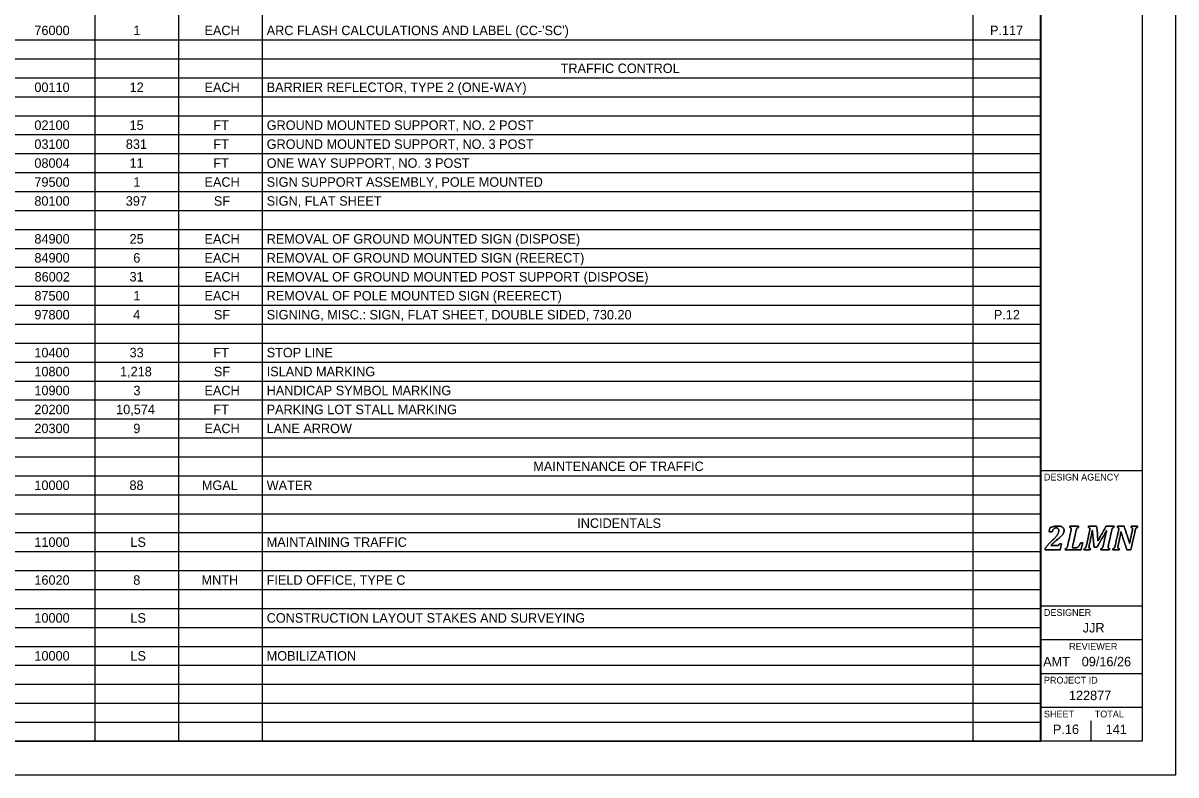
# Model space of a CAD drawing. Extents: x 0 to 34, y 0 to 22.
# Drawn here: x 16.98 to 34, y 0 to 11.11 of the extents above; entities that cross this region are included whole.
import ezdxf

# ---------------------------------------------------------------- set-up
doc = ezdxf.new("R2010")
doc.units = 0
for name, color, linetype in [('SH_Border', 7, 'Continuous'), ('SH_Cut_Line', 7, 'Continuous'), ('SH_Data', 7, 'Continuous'), ('SH_Text', 7, 'Continuous')]:
    doc.layers.add(name, color=color, linetype=linetype)

msp = doc.modelspace()

# ---------------------------------------------------------------- linework, layer by layer
at = {"layer": 'SH_Border'}
for p, q in [((32, 0.5), (32, 21.5)), ((32, 4.5), (33.5, 4.5)), ((32, 2.5), (33.5, 2.5)), ((32, 2), (33.5, 2)), ((32, 1.5), (33.5, 1.5)), ((32, 1), (33.5, 1))]:
    msp.add_line(p, q, dxfattribs=at)
msp.add_lwpolyline([(1.5, 21.5), (33.5, 21.5), (33.5, 0.5), (1.5, 0.5)], close=True, dxfattribs=at)
at = {"layer": 'SH_Cut_Line'}
msp.add_lwpolyline([(0, 0), (34, 0), (34, 22), (0, 22)], close=True, dxfattribs=at)
at = {"layer": 'SH_Data'}
for p, q in [((32.75, 3.5), (32.75, 3.5)), ((32.75, 0.5), (32.75, 0.8)), ((32.375, 0.675), (32.375, 0.675))]:
    msp.add_line(p, q, dxfattribs=at)
for points in [[(32.237, 3.388), (32.246, 3.388), (32.253, 3.389), (32.258, 3.39), (32.263, 3.392), (32.267, 3.394), (32.27, 3.397), (32.273, 3.401), (32.277, 3.408), (32.281, 3.417), (32.281, 3.417), (32.312, 3.417), (32.312, 3.417), (32.312, 3.417), (32.29, 3.326), (32.29, 3.326), (32.29, 3.326), (32.066, 3.326), (32.066, 3.326), (32.066, 3.326), (32.069, 3.343), (32.069, 3.343), (32.078, 3.358), (32.091, 3.375), (32.106, 3.394), (32.122, 3.412), (32.144, 3.435), (32.172, 3.462), (32.197, 3.486), (32.217, 3.506), (32.23, 3.521), (32.243, 3.537), (32.253, 3.551), (32.259, 3.566), (32.266, 3.58), (32.269, 3.595), (32.269, 3.61), (32.269, 3.622), (32.266, 3.632), (32.26, 3.64), (32.253, 3.647), (32.245, 3.65), (32.234, 3.65), (32.22, 3.65), (32.208, 3.646), (32.198, 3.636), (32.188, 3.627), (32.18, 3.613), (32.172, 3.593), (32.172, 3.593), (32.126, 3.593), (32.126, 3.593), (32.126, 3.593), (32.14, 3.654), (32.14, 3.654), (32.166, 3.663), (32.188, 3.669), (32.205, 3.673), (32.223, 3.676), (32.24, 3.678), (32.258, 3.678), (32.278, 3.678), (32.295, 3.675), (32.309, 3.669), (32.322, 3.664), (32.332, 3.656), (32.339, 3.646), (32.345, 3.637), (32.348, 3.626), (32.348, 3.613), (32.348, 3.602), (32.346, 3.591), (32.342, 3.581), (32.339, 3.571), (32.333, 3.56), (32.324, 3.549), (32.315, 3.539), (32.304, 3.526), (32.289, 3.513), (32.275, 3.499), (32.254, 3.482), (32.228, 3.46), (32.216, 3.45), (32.202, 3.438), (32.188, 3.425), (32.174, 3.412), (32.162, 3.4), (32.154, 3.391), (32.154, 3.391), (32.153, 3.388), (32.153, 3.388), (32.153, 3.388), (32.237, 3.388), (32.237, 3.388)], [(32.237, 3.388), (32.237, 3.388), (32.153, 3.388), (32.153, 3.388), (32.153, 3.388), (32.154, 3.391), (32.154, 3.391), (32.162, 3.4), (32.174, 3.412), (32.188, 3.425), (32.202, 3.438), (32.216, 3.45), (32.228, 3.46), (32.254, 3.482), (32.275, 3.499), (32.289, 3.513), (32.304, 3.526), (32.315, 3.539), (32.324, 3.549), (32.333, 3.56), (32.339, 3.571), (32.342, 3.581), (32.346, 3.591), (32.348, 3.602), (32.348, 3.613), (32.348, 3.626), (32.345, 3.637), (32.339, 3.646), (32.332, 3.656), (32.322, 3.664), (32.309, 3.669), (32.295, 3.675), (32.278, 3.678), (32.258, 3.678), (32.24, 3.678), (32.223, 3.676), (32.205, 3.673), (32.188, 3.669), (32.166, 3.663), (32.14, 3.654), (32.14, 3.654), (32.126, 3.593), (32.126, 3.593), (32.126, 3.593), (32.172, 3.593), (32.172, 3.593), (32.18, 3.613), (32.188, 3.627), (32.198, 3.636), (32.208, 3.646), (32.22, 3.65), (32.234, 3.65), (32.245, 3.65), (32.253, 3.647), (32.26, 3.64), (32.266, 3.632), (32.269, 3.622), (32.269, 3.61), (32.269, 3.595), (32.266, 3.58), (32.259, 3.566), (32.253, 3.551), (32.243, 3.537), (32.23, 3.521), (32.217, 3.506), (32.197, 3.486), (32.172, 3.462), (32.144, 3.435), (32.122, 3.412), (32.106, 3.394), (32.091, 3.375), (32.078, 3.358), (32.069, 3.343), (32.069, 3.343), (32.066, 3.326), (32.066, 3.326), (32.066, 3.326), (32.29, 3.326), (32.29, 3.326), (32.29, 3.326), (32.312, 3.417), (32.312, 3.417), (32.312, 3.417), (32.281, 3.417), (32.281, 3.417), (32.277, 3.408), (32.273, 3.401), (32.27, 3.397), (32.267, 3.394), (32.263, 3.392), (32.258, 3.39), (32.253, 3.389), (32.246, 3.388), (32.237, 3.388)], [(32.518, 3.356), (32.527, 3.356), (32.533, 3.357), (32.538, 3.358), (32.542, 3.36), (32.546, 3.362), (32.55, 3.365), (32.554, 3.368), (32.558, 3.372), (32.562, 3.377), (32.567, 3.382), (32.571, 3.388), (32.576, 3.397), (32.58, 3.405), (32.585, 3.415), (32.589, 3.427), (32.589, 3.427), (32.624, 3.427), (32.624, 3.427), (32.624, 3.427), (32.598, 3.326), (32.598, 3.326), (32.598, 3.326), (32.365, 3.326), (32.365, 3.326), (32.365, 3.326), (32.369, 3.343), (32.369, 3.343), (32.376, 3.345), (32.381, 3.348), (32.385, 3.351), (32.389, 3.355), (32.392, 3.36), (32.395, 3.366), (32.398, 3.373), (32.4, 3.382), (32.403, 3.395), (32.403, 3.395), (32.449, 3.605), (32.449, 3.605), (32.452, 3.615), (32.453, 3.625), (32.453, 3.635), (32.453, 3.642), (32.451, 3.647), (32.448, 3.651), (32.444, 3.654), (32.439, 3.656), (32.432, 3.657), (32.432, 3.657), (32.435, 3.674), (32.435, 3.674), (32.435, 3.674), (32.563, 3.674), (32.563, 3.674), (32.563, 3.674), (32.559, 3.657), (32.559, 3.657), (32.552, 3.655), (32.547, 3.652), (32.543, 3.649), (32.539, 3.645), (32.536, 3.64), (32.533, 3.634), (32.531, 3.627), (32.528, 3.618), (32.525, 3.605), (32.525, 3.605), (32.47, 3.356), (32.47, 3.356), (32.47, 3.356), (32.518, 3.356), (32.518, 3.356)], [(32.518, 3.356), (32.518, 3.356), (32.47, 3.356), (32.47, 3.356), (32.47, 3.356), (32.525, 3.605), (32.525, 3.605), (32.528, 3.618), (32.531, 3.627), (32.533, 3.634), (32.536, 3.64), (32.539, 3.645), (32.543, 3.649), (32.547, 3.652), (32.552, 3.655), (32.559, 3.657), (32.559, 3.657), (32.563, 3.674), (32.563, 3.674), (32.563, 3.674), (32.435, 3.674), (32.435, 3.674), (32.435, 3.674), (32.432, 3.657), (32.432, 3.657), (32.439, 3.656), (32.444, 3.654), (32.448, 3.651), (32.451, 3.647), (32.453, 3.642), (32.453, 3.635), (32.453, 3.625), (32.452, 3.615), (32.449, 3.605), (32.449, 3.605), (32.403, 3.395), (32.403, 3.395), (32.4, 3.382), (32.398, 3.373), (32.395, 3.366), (32.392, 3.36), (32.389, 3.355), (32.385, 3.351), (32.381, 3.348), (32.376, 3.345), (32.369, 3.343), (32.369, 3.343), (32.365, 3.326), (32.365, 3.326), (32.365, 3.326), (32.598, 3.326), (32.598, 3.326), (32.598, 3.326), (32.624, 3.427), (32.624, 3.427), (32.624, 3.427), (32.589, 3.427), (32.589, 3.427), (32.585, 3.415), (32.58, 3.405), (32.576, 3.397), (32.571, 3.388), (32.567, 3.382), (32.562, 3.377), (32.558, 3.372), (32.554, 3.368), (32.55, 3.365), (32.546, 3.362), (32.542, 3.36), (32.538, 3.358), (32.533, 3.357), (32.527, 3.356), (32.518, 3.356)], [(32.829, 3.674), (32.829, 3.674), (32.849, 3.461), (32.849, 3.461), (32.849, 3.461), (32.969, 3.674), (32.969, 3.674), (32.969, 3.674), (33.087, 3.674), (33.087, 3.674), (33.087, 3.674), (33.084, 3.657), (33.084, 3.657), (33.077, 3.655), (33.071, 3.652), (33.067, 3.649), (33.064, 3.645), (33.06, 3.64), (33.058, 3.634), (33.055, 3.627), (33.052, 3.618), (33.05, 3.605), (33.05, 3.605), (33.003, 3.395), (33.003, 3.395), (33.002, 3.39), (33.002, 3.387), (33.001, 3.384), (33.001, 3.382), (33.001, 3.379), (33, 3.376), (33, 3.373), (33, 3.369), (33, 3.365), (33, 3.358), (33.002, 3.353), (33.005, 3.349), (33.008, 3.346), (33.014, 3.344), (33.021, 3.343), (33.021, 3.343), (33.018, 3.326), (33.018, 3.326), (33.018, 3.326), (32.89, 3.326), (32.89, 3.326), (32.89, 3.326), (32.893, 3.343), (32.893, 3.343), (32.9, 3.345), (32.906, 3.348), (32.91, 3.351), (32.914, 3.355), (32.917, 3.36), (32.919, 3.366), (32.922, 3.373), (32.925, 3.382), (32.928, 3.395), (32.928, 3.395), (32.951, 3.502), (32.951, 3.502), (32.954, 3.513), (32.957, 3.529), (32.962, 3.548), (32.967, 3.568), (32.972, 3.588), (32.978, 3.609), (32.978, 3.609), (32.973, 3.609), (32.973, 3.609), (32.965, 3.594), (32.957, 3.579), (32.948, 3.563), (32.948, 3.563), (32.833, 3.364), (32.833, 3.364), (32.833, 3.364), (32.792, 3.364), (32.792, 3.364), (32.792, 3.364), (32.775, 3.518), (32.775, 3.518), (32.773, 3.537), (32.772, 3.554), (32.77, 3.569), (32.769, 3.583), (32.768, 3.597), (32.768, 3.611), (32.768, 3.611), (32.764, 3.611), (32.764, 3.611), (32.761, 3.596), (32.758, 3.578), (32.755, 3.558), (32.751, 3.538), (32.747, 3.521), (32.744, 3.507), (32.744, 3.507), (32.72, 3.395), (32.72, 3.395), (32.719, 3.39), (32.718, 3.387), (32.718, 3.384), (32.717, 3.382), (32.717, 3.379), (32.717, 3.376), (32.717, 3.373), (32.716, 3.369), (32.716, 3.365), (32.716, 3.358), (32.718, 3.353), (32.721, 3.349), (32.725, 3.346), (32.73, 3.344), (32.738, 3.343), (32.738, 3.343), (32.734, 3.326), (32.734, 3.326), (32.734, 3.326), (32.641, 3.326), (32.641, 3.326), (32.641, 3.326), (32.644, 3.343), (32.644, 3.343), (32.651, 3.345), (32.657, 3.348), (32.661, 3.351), (32.665, 3.355), (32.668, 3.36), (32.67, 3.366), (32.673, 3.373), (32.676, 3.382), (32.679, 3.395), (32.679, 3.395), (32.725, 3.605), (32.725, 3.605), (32.727, 3.615), (32.728, 3.625), (32.728, 3.635), (32.728, 3.642), (32.727, 3.647), (32.723, 3.651), (32.72, 3.654), (32.715, 3.656), (32.707, 3.657), (32.707, 3.657), (32.711, 3.674), (32.711, 3.674), (32.711, 3.674), (32.829, 3.674), (32.829, 3.674)], [(32.829, 3.674), (32.829, 3.674), (32.711, 3.674), (32.711, 3.674), (32.711, 3.674), (32.707, 3.657), (32.707, 3.657), (32.715, 3.656), (32.72, 3.654), (32.723, 3.651), (32.727, 3.647), (32.728, 3.642), (32.728, 3.635), (32.728, 3.625), (32.727, 3.615), (32.725, 3.605), (32.725, 3.605), (32.679, 3.395), (32.679, 3.395), (32.676, 3.382), (32.673, 3.373), (32.67, 3.366), (32.668, 3.36), (32.665, 3.355), (32.661, 3.351), (32.657, 3.348), (32.651, 3.345), (32.644, 3.343), (32.644, 3.343), (32.641, 3.326), (32.641, 3.326), (32.641, 3.326), (32.734, 3.326), (32.734, 3.326), (32.734, 3.326), (32.738, 3.343), (32.738, 3.343), (32.73, 3.344), (32.725, 3.346), (32.721, 3.349), (32.718, 3.353), (32.716, 3.358), (32.716, 3.365), (32.716, 3.369), (32.717, 3.373), (32.717, 3.376), (32.717, 3.379), (32.717, 3.382), (32.718, 3.384), (32.718, 3.387), (32.719, 3.39), (32.72, 3.395), (32.72, 3.395), (32.744, 3.507), (32.744, 3.507), (32.747, 3.521), (32.751, 3.538), (32.755, 3.558), (32.758, 3.578), (32.761, 3.596), (32.764, 3.611), (32.764, 3.611), (32.768, 3.611), (32.768, 3.611), (32.768, 3.597), (32.769, 3.583), (32.77, 3.569), (32.772, 3.554), (32.773, 3.537), (32.775, 3.518), (32.775, 3.518), (32.792, 3.364), (32.792, 3.364), (32.792, 3.364), (32.833, 3.364), (32.833, 3.364), (32.833, 3.364), (32.948, 3.563), (32.948, 3.563), (32.957, 3.579), (32.965, 3.594), (32.973, 3.609), (32.973, 3.609), (32.978, 3.609), (32.978, 3.609), (32.972, 3.588), (32.967, 3.568), (32.962, 3.548), (32.957, 3.529), (32.954, 3.513), (32.951, 3.502), (32.951, 3.502), (32.928, 3.395), (32.928, 3.395), (32.925, 3.382), (32.922, 3.373), (32.919, 3.366), (32.917, 3.36), (32.914, 3.355), (32.91, 3.351), (32.906, 3.348), (32.9, 3.345), (32.893, 3.343), (32.893, 3.343), (32.89, 3.326), (32.89, 3.326), (32.89, 3.326), (33.018, 3.326), (33.018, 3.326), (33.018, 3.326), (33.021, 3.343), (33.021, 3.343), (33.014, 3.344), (33.008, 3.346), (33.005, 3.349), (33.002, 3.353), (33, 3.358), (33, 3.365), (33, 3.369), (33, 3.373), (33, 3.376), (33.001, 3.379), (33.001, 3.382), (33.001, 3.384), (33.002, 3.387), (33.002, 3.39), (33.003, 3.395), (33.003, 3.395), (33.05, 3.605), (33.05, 3.605), (33.052, 3.618), (33.055, 3.627), (33.058, 3.634), (33.06, 3.64), (33.064, 3.645), (33.067, 3.649), (33.071, 3.652), (33.077, 3.655), (33.084, 3.657), (33.084, 3.657), (33.087, 3.674), (33.087, 3.674), (33.087, 3.674), (32.969, 3.674), (32.969, 3.674), (32.969, 3.674), (32.849, 3.461), (32.849, 3.461), (32.849, 3.461), (32.829, 3.674), (32.829, 3.674)], [(33.137, 3.674), (33.137, 3.674), (33.234, 3.674), (33.234, 3.674), (33.234, 3.674), (33.283, 3.53), (33.283, 3.53), (33.296, 3.49), (33.307, 3.456), (33.315, 3.426), (33.315, 3.426), (33.318, 3.426), (33.318, 3.426), (33.323, 3.455), (33.329, 3.488), (33.337, 3.523), (33.337, 3.523), (33.355, 3.605), (33.355, 3.605), (33.357, 3.615), (33.358, 3.625), (33.358, 3.635), (33.358, 3.642), (33.357, 3.647), (33.353, 3.651), (33.35, 3.654), (33.345, 3.656), (33.337, 3.657), (33.337, 3.657), (33.341, 3.674), (33.341, 3.674), (33.341, 3.674), (33.434, 3.674), (33.434, 3.674), (33.434, 3.674), (33.431, 3.657), (33.431, 3.657), (33.424, 3.655), (33.418, 3.652), (33.414, 3.649), (33.41, 3.645), (33.407, 3.64), (33.405, 3.634), (33.402, 3.627), (33.399, 3.618), (33.396, 3.605), (33.396, 3.605), (33.335, 3.326), (33.335, 3.326), (33.335, 3.326), (33.277, 3.326), (33.277, 3.326), (33.277, 3.326), (33.216, 3.504), (33.216, 3.504), (33.211, 3.518), (33.207, 3.531), (33.204, 3.543), (33.2, 3.556), (33.195, 3.571), (33.19, 3.59), (33.19, 3.59), (33.186, 3.59), (33.186, 3.59), (33.185, 3.579), (33.182, 3.563), (33.179, 3.543), (33.175, 3.523), (33.17, 3.501), (33.165, 3.478), (33.165, 3.478), (33.147, 3.395), (33.147, 3.395), (33.146, 3.39), (33.145, 3.387), (33.145, 3.384), (33.144, 3.382), (33.144, 3.379), (33.144, 3.376), (33.143, 3.373), (33.143, 3.369), (33.143, 3.365), (33.143, 3.358), (33.145, 3.353), (33.148, 3.349), (33.152, 3.346), (33.157, 3.344), (33.164, 3.343), (33.164, 3.343), (33.161, 3.326), (33.161, 3.326), (33.161, 3.326), (33.067, 3.326), (33.067, 3.326), (33.067, 3.326), (33.071, 3.343), (33.071, 3.343), (33.078, 3.345), (33.083, 3.348), (33.087, 3.351), (33.091, 3.355), (33.094, 3.36), (33.097, 3.366), (33.1, 3.373), (33.102, 3.382), (33.105, 3.395), (33.105, 3.395), (33.151, 3.605), (33.151, 3.605), (33.154, 3.615), (33.155, 3.625), (33.155, 3.635), (33.155, 3.642), (33.153, 3.647), (33.15, 3.651), (33.146, 3.654), (33.141, 3.656), (33.134, 3.657), (33.134, 3.657), (33.137, 3.674), (33.137, 3.674)], [(33.137, 3.674), (33.137, 3.674), (33.134, 3.657), (33.134, 3.657), (33.141, 3.656), (33.146, 3.654), (33.15, 3.651), (33.153, 3.647), (33.155, 3.642), (33.155, 3.635), (33.155, 3.625), (33.154, 3.615), (33.151, 3.605), (33.151, 3.605), (33.105, 3.395), (33.105, 3.395), (33.102, 3.382), (33.1, 3.373), (33.097, 3.366), (33.094, 3.36), (33.091, 3.355), (33.087, 3.351), (33.083, 3.348), (33.078, 3.345), (33.071, 3.343), (33.071, 3.343), (33.067, 3.326), (33.067, 3.326), (33.067, 3.326), (33.161, 3.326), (33.161, 3.326), (33.161, 3.326), (33.164, 3.343), (33.164, 3.343), (33.157, 3.344), (33.152, 3.346), (33.148, 3.349), (33.145, 3.353), (33.143, 3.358), (33.143, 3.365), (33.143, 3.369), (33.143, 3.373), (33.144, 3.376), (33.144, 3.379), (33.144, 3.382), (33.145, 3.384), (33.145, 3.387), (33.146, 3.39), (33.147, 3.395), (33.147, 3.395), (33.165, 3.478), (33.165, 3.478), (33.17, 3.501), (33.175, 3.523), (33.179, 3.543), (33.182, 3.563), (33.185, 3.579), (33.186, 3.59), (33.186, 3.59), (33.19, 3.59), (33.19, 3.59), (33.195, 3.571), (33.2, 3.556), (33.204, 3.543), (33.207, 3.531), (33.211, 3.518), (33.216, 3.504), (33.216, 3.504), (33.277, 3.326), (33.277, 3.326), (33.277, 3.326), (33.335, 3.326), (33.335, 3.326), (33.335, 3.326), (33.396, 3.605), (33.396, 3.605), (33.399, 3.618), (33.402, 3.627), (33.405, 3.634), (33.407, 3.64), (33.41, 3.645), (33.414, 3.649), (33.418, 3.652), (33.424, 3.655), (33.431, 3.657), (33.431, 3.657), (33.434, 3.674), (33.434, 3.674), (33.434, 3.674), (33.341, 3.674), (33.341, 3.674), (33.341, 3.674), (33.337, 3.657), (33.337, 3.657), (33.345, 3.656), (33.35, 3.654), (33.353, 3.651), (33.357, 3.647), (33.358, 3.642), (33.358, 3.635), (33.358, 3.625), (33.357, 3.615), (33.355, 3.605), (33.355, 3.605), (33.337, 3.523), (33.337, 3.523), (33.329, 3.488), (33.323, 3.455), (33.318, 3.426), (33.318, 3.426), (33.315, 3.426), (33.315, 3.426), (33.307, 3.456), (33.296, 3.49), (33.283, 3.53), (33.283, 3.53), (33.234, 3.674), (33.234, 3.674), (33.234, 3.674), (33.137, 3.674), (33.137, 3.674)]]:
    msp.add_open_spline(points, degree=3, dxfattribs=at)
at = {"layer": 'SH_Text'}
for p, q in [((18.036, 21.5), (18.036, 0.5)), ((19.272, 21.5), (19.272, 0.5)), ((20.507, 21.5), (20.507, 0.5)), ((30.999, 21.5), (30.999, 0.5)), ((32.004, 21.5), (32.004, 0.5)), ((1.5, 10.86), (32.004, 10.86)), ((1.5, 10.58), (32.004, 10.58)), ((1.5, 10.3), (32.004, 10.3)), ((1.5, 10.02), (32.004, 10.02)), ((1.5, 9.74), (32.004, 9.74)), ((1.5, 9.46), (32.004, 9.46)), ((1.5, 9.18), (32.004, 9.18)), ((1.5, 8.9), (32.004, 8.9)), ((1.5, 8.62), (32.004, 8.62)), ((1.5, 8.34), (32.004, 8.34)), ((1.5, 8.06), (32.004, 8.06)), ((1.5, 7.78), (32.004, 7.78)), ((1.5, 7.5), (32.004, 7.5)), ((1.5, 7.22), (32.004, 7.22)), ((1.5, 6.94), (32.004, 6.94)), ((1.5, 6.66), (32.004, 6.66)), ((1.5, 6.38), (32.004, 6.38)), ((1.5, 6.1), (32.004, 6.1)), ((1.5, 5.82), (32.004, 5.82)), ((1.5, 5.54), (32.004, 5.54)), ((1.5, 5.26), (32.004, 5.26)), ((1.5, 4.98), (32.004, 4.98)), ((1.5, 4.7), (32.004, 4.7)), ((1.5, 4.42), (32.004, 4.42)), ((1.5, 4.14), (32.004, 4.14)), ((1.5, 3.86), (32.004, 3.86)), ((1.5, 3.58), (32.004, 3.58)), ((1.5, 3.3), (32.004, 3.3)), ((1.5, 3.02), (32.004, 3.02)), ((1.5, 2.74), (32.004, 2.74)), ((1.5, 2.46), (32.004, 2.46)), ((1.5, 2.18), (32.004, 2.18)), ((1.5, 1.9), (32.004, 1.9)), ((1.5, 1.62), (32.004, 1.62)), ((1.5, 1.34), (32.004, 1.34)), ((1.5, 1.06), (32.004, 1.06)), ((1.5, 0.78), (32.004, 0.78)), ((1.5, 0.5), (32.004, 0.5))]:
    msp.add_line(p, q, dxfattribs=at)

# ---------------------------------------------------------------- texts
at = {"layer": 'SH_Data'}
for s, height, p in [('DESIGN AGENCY', 0.1, (32.05, 4.35)), ('DESIGNER', 0.1, (32.05, 2.35)), ('JJR', 0.14, (32.624, 2.105)), ('REVIEWER', 0.1, (32.422, 1.85)), ('AMT', 0.14, (32.039, 1.605)), ('09/16/26', 0.14, (32.609, 1.605)), ('PROJECT ID', 0.1, (32.05, 1.35)), ('122877', 0.14, (32.42, 1.105)), ('SHEET', 0.1, (32.05, 0.85)), ('TOTAL', 0.1, (32.8, 0.85)), ('P.16', 0.14, (32.183, 0.605)), ('141', 0.14, (32.963, 0.605))]:
    msp.add_text(s, height=height, dxfattribs=at).set_placement(p)
at = {"layer": 'SH_Text'}
for s, p in [('76000', (17.143, 10.93)), ('1', (18.604, 10.93)), ('EACH', (19.655, 10.93)), ("ARC FLASH CALCULATIONS AND LABEL (CC-'SC')", (20.573, 10.93)), ('P.117', (31.254, 10.93)), ('TRAFFIC CONTROL', (24.914, 10.37)), ('00110', (17.143, 10.09)), ('12', (18.549, 10.09)), ('EACH', (19.655, 10.09)), ('BARRIER REFLECTOR, TYPE 2 (ONE-WAY)', (20.573, 10.09)), ('02100', (17.143, 9.53)), ('15', (18.549, 9.53)), ('FT', (19.786, 9.53)), ('GROUND MOUNTED SUPPORT, NO. 2 POST', (20.573, 9.53)), ('03100', (17.143, 9.25)), ('831', (18.493, 9.25)), ('FT', (19.786, 9.25)), ('GROUND MOUNTED SUPPORT, NO. 3 POST', (20.573, 9.25)), ('08004', (17.143, 8.97)), ('11', (18.548, 8.97)), ('FT', (19.786, 8.97)), ('ONE WAY SUPPORT, NO. 3 POST', (20.573, 8.97)), ('79500', (17.143, 8.69)), ('1', (18.604, 8.69)), ('EACH', (19.655, 8.69)), ('SIGN SUPPORT ASSEMBLY, POLE MOUNTED', (20.573, 8.69)), ('80100', (17.143, 8.41)), ('397', (18.492, 8.41)), ('SF', (19.793, 8.41)), ('SIGN, FLAT SHEET', (20.573, 8.41)), ('84900', (17.143, 7.85)), ('25', (18.549, 7.85)), ('EACH', (19.655, 7.85)), ('REMOVAL OF GROUND MOUNTED SIGN (DISPOSE)', (20.573, 7.85)), ('84900', (17.143, 7.57)), ('6', (18.603, 7.57)), ('EACH', (19.655, 7.57)), ('REMOVAL OF GROUND MOUNTED SIGN (REERECT)', (20.573, 7.57)), ('86002', (17.146, 7.29)), ('31', (18.548, 7.29)), ('EACH', (19.655, 7.29)), ('REMOVAL OF GROUND MOUNTED POST SUPPORT (DISPOSE)', (20.573, 7.29)), ('87500', (17.143, 7.01)), ('EACH', (19.655, 7.01)), ('REMOVAL OF POLE MOUNTED SIGN (REERECT)', (20.573, 7.01)), ('1', (18.604, 7.01)), ('97800', (17.143, 6.73)), ('4', (18.601, 6.73)), ('SF', (19.793, 6.73)), ('SIGNING, MISC.: SIGN, FLAT SHEET, DOUBLE SIDED, 730.20', (20.573, 6.73)), ('P.12', (31.311, 6.73)), ('10400', (17.143, 6.17)), ('33', (18.549, 6.17)), ('FT', (19.786, 6.17)), ('STOP LINE', (20.573, 6.17)), ('10800', (17.143, 5.89)), ('1,218', (18.408, 5.89)), ('SF', (19.793, 5.89)), ('ISLAND MARKING', (20.573, 5.89)), ('10900', (17.143, 5.61)), ('3', (18.605, 5.61)), ('EACH', (19.655, 5.61)), ('HANDICAP SYMBOL MARKING', (20.573, 5.61)), ('20200', (17.143, 5.33)), ('10,574', (18.35, 5.33)), ('FT', (19.786, 5.33)), ('PARKING LOT STALL MARKING', (20.573, 5.33)), ('20300', (17.143, 5.05)), ('9', (18.604, 5.05)), ('EACH', (19.655, 5.05)), ('LANE ARROW', (20.573, 5.05)), ('MAINTENANCE OF TRAFFIC', (24.51, 4.49)), ('10000', (17.143, 4.21)), ('88', (18.547, 4.21)), ('MGAL', (19.616, 4.21)), ('WATER', (20.573, 4.21)), ('INCIDENTALS', (25.159, 3.65)), ('11000', (17.143, 3.37)), ('LS', (18.561, 3.37)), ('MAINTAINING TRAFFIC', (20.573, 3.37)), ('16020', (17.143, 2.81)), ('8', (18.603, 2.81)), ('MNTH', (19.611, 2.81)), ('FIELD OFFICE, TYPE C', (20.573, 2.81)), ('10000', (17.143, 2.25)), ('LS', (18.561, 2.25)), ('CONSTRUCTION LAYOUT STAKES AND SURVEYING', (20.573, 2.25)), ('10000', (17.143, 1.69)), ('LS', (18.561, 1.69)), ('MOBILIZATION', (20.573, 1.69))]:
    msp.add_text(s, height=0.14, dxfattribs=at).set_placement(p)

doc.saveas('drawing.dxf')
